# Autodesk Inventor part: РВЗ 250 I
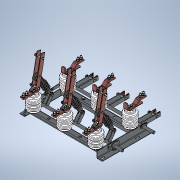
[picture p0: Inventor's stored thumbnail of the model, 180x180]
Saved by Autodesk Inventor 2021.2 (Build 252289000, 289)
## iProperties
Created: 1900-01
Part Number: РВЗ 250 I
Material: Типовые
Description: STEP AP242
Document SubType Name: Modeling
Designer: pc
Density: 1 g/cm^3
Appearance: По умолчанию
Company: UNSPECIFIED
Title: ÐÂÇ 250 I
Author: UNSPECIFIED
Revision Number: ANYUNSPECIFIED
Sending System: C3D Toolkit
Preprocessor: C3D Converter
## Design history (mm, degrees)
feature "БазТело1"
feature "БазТело2"
feature "БазТело3"
feature "БазТело4"
feature "Составной1"
node "Твердое тело1"
node "Твердое тело2"
node "Твердое тело3"
node "Твердое тело4"
body "SRF1"
